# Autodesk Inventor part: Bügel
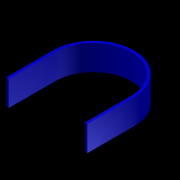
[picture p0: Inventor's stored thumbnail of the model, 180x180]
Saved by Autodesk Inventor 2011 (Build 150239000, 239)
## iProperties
Created: 2012-06
Part Number: Bügel
Document SubType Name: Modeling
Designer: M.Schulte
Density: 1 g/cm^3
Author: M.Schulte
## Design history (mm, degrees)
sketch "Skizze1"
  geometry: L1 (-45, 0)-(-45, 55); L2 (45, 55)-(45, 0); L3 (-48, 0)-(-48, 55); L4 (48, 55)-(48, 0); L5 (-48, 0)-(-45, 0); L6 (45, 0)-(48, 0); A1 r 45 centre (0, 55) between (45, 55) and (-45, 55); A2 r 48 centre (0, 55) between (48, 55) and (-48, 55); 1 further point
  constraints: 12 end point, 4 point on circle, 3 equal length, 2 centre point, 2 horizontal alignment, 2 tangent, 1 perpendicular, 1 vertical, 1 vertical alignment, 2 other
  dimensions: "d0" = 45 radius of A1; "d1" = 55 distance of L2.start L2.end; "d2" = 3 distance of L3.start L1.start
extrude "Extrusion1" new body sketch "Skizze1" distance "d3" = 30; taper "d4" = 0 deg
node "Volumenkörper1"
